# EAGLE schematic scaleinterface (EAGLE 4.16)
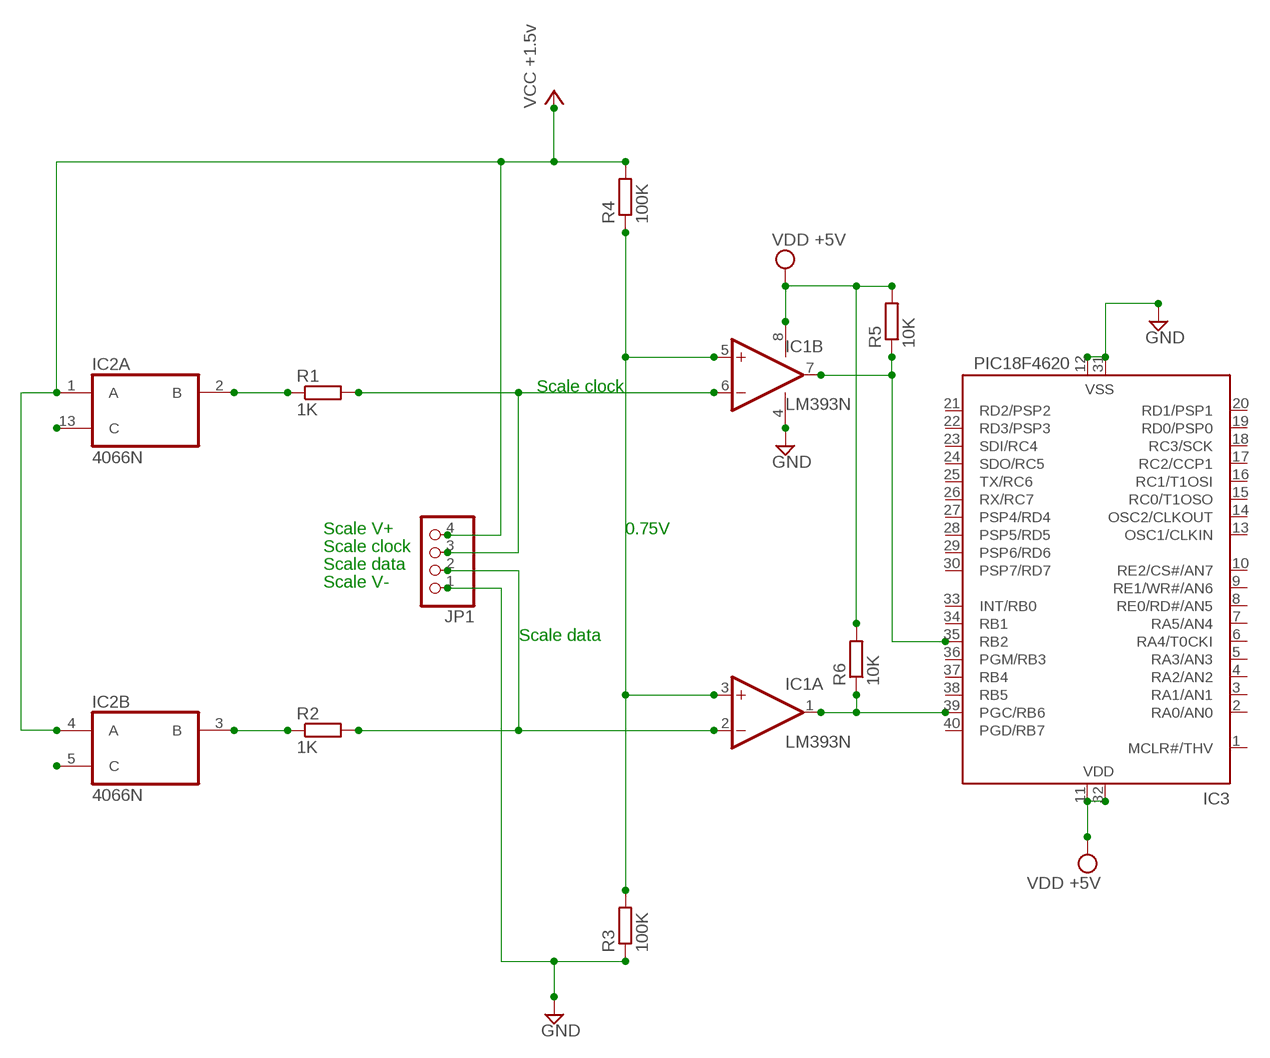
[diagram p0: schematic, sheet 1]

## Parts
IC1  LM393N  [DIL08]
IC2  4066N  [DIL14]
IC3  PIC18F4620  PIC16F874P  [DIL40]
JP1  PINHD-1X4  [1X04]
R1  1K  R-EU_0204/5  [0204/5]
R2  1K  R-EU_0204/5  [0204/5]
R3  100K  R-EU_0204/5  [0204/5]
R4  100K  R-EU_0204/5  [0204/5]
R5  10K  R-EU_0204/5  [0204/5]
R6  10K  R-EU_0204/5  [0204/5]

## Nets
GND: IC1.4(P:V-) IC3.12(VSS) IC3.31(VSS) JP1.1 R3.1
N$1: IC1.3(A:+IN) IC1.5(B:+IN) R3.2 R4.1
N$2: IC1.1(A:OUT) IC3.39(PGC/RB6) R6.1
N$5: IC1.7(B:OUT) IC3.35(RB2) R5.1
N$9: IC2.2(A:B) R1.1
N$15: IC1.2(A:-IN) JP1.2 R2.2
N$16: IC1.6(B:-IN) JP1.3 R1.2
N$19: IC2.5(B:C)
N$21: IC2.13(A:C)
N$22: IC2.3(B:B) R2.1
VCC: IC2.1(A:A) IC2.4(B:A) JP1.4 R4.2 ; supply symbol labelled VCC +1.5v
VDD: IC1.8(P:V+) IC3.11(VDD) IC3.32(VDD) R5.2 R6.2 ; supply symbol labelled VDD +5V
Unconnected: IC2.6(C:C) IC2.8(C:A) IC2.9(C:B) IC2.10(D:B) IC2.11(D:A) IC2.12(D:C) IC3.1(MCLR#/THV) IC3.2(RA0/AN0) IC3.3(RA1/AN1) IC3.4(RA2/AN2) IC3.5(RA3/AN3) IC3.6(RA4/T0CKI) IC3.7(RA5/AN4) IC3.8(RE0/RD#/AN5) IC3.9(RE1/WR#/AN6) IC3.10(RE2/CS#/AN7) IC3.13(OSC1/CLKIN) IC3.14(OSC2/CLKOUT) IC3.15(RC0/T1OSO) IC3.16(RC1/T1OSI) IC3.17(RC2/CCP1) IC3.18(RC3/SCK) IC3.19(RD0/PSP0) IC3.20(RD1/PSP1) IC3.21(RD2/PSP2) IC3.22(RD3/PSP3) IC3.23(SDI/RC4) IC3.24(SDO/RC5) IC3.25(TX/RC6) IC3.26(RX/RC7) IC3.27(PSP4/RD4) IC3.28(PSP5/RD5) IC3.29(PSP6/RD6) IC3.30(PSP7/RD7) IC3.33(INT/RB0) IC3.34(RB1) IC3.36(PGM/RB3) IC3.37(RB4) IC3.38(RB5) IC3.40(PGD/RB7)

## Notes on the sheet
- Scale clock
- Scale V+ | 0.75V
- Scale clock
- Scale data
- Scale V-
- Scale data

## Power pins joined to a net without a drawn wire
VDD: IC2.14(P:VDD)
VSS: IC2.7(P:VSS)

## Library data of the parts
IC1 = linear:LM393: COMPARATOR
IC2 = 40xx:4066: Quad bilateral ANALOG SWITCH
IC3 = microchip:PIC16F87*: MICROCONTROLLER
JP1 = pinhead:PINHD-1X4: PIN HEADER
R1-R6 = rcl:R-EU_: RESISTOR, European symbol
